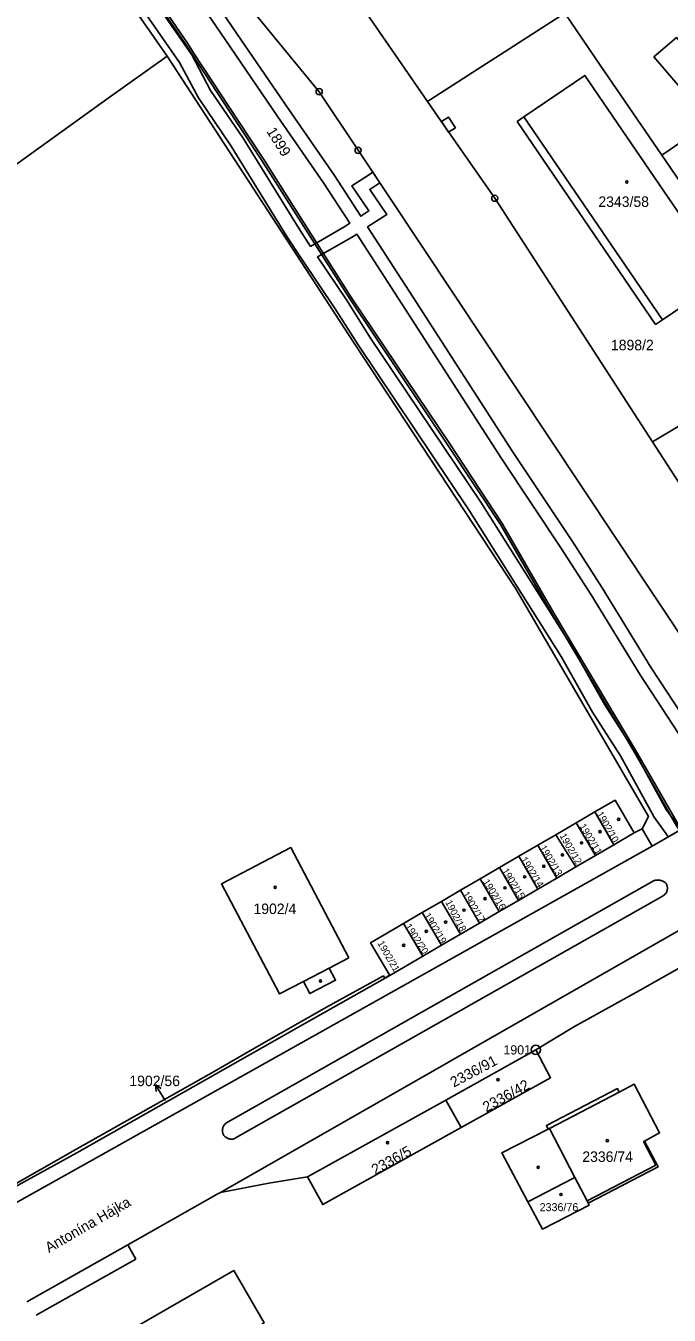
# Model space of a CAD drawing. Extents: x -821458 to -820266, y -1071458 to -1069826.
# Drawn here: x -820951.1 to -820846.6, y -1071063.4 to -1070854 of the extents above; entities that cross this region are included whole.
import ezdxf

# ---------------------------------------------------------------- set-up
doc = ezdxf.new("R2010")
doc.units = 0
for name, color, linetype in [('Vrstva 1', 7, 'Continuous'), ('Vrstva 13', 7, 'Continuous'), ('Vrstva 2', 7, 'Continuous'), ('Vrstva 4', 7, 'Continuous'), ('Vrstva 5', 7, 'Continuous'), ('Vrstva 7', 7, 'Continuous'), ('Vrstva 8', 7, 'Continuous')]:
    doc.layers.add(name, color=color, linetype=linetype)

msp = doc.modelspace()

# ---------------------------------------------------------------- linework, layer by layer
at = {"layer": 'Vrstva 1'}
for p, q in [((-820969.81, -1070799.27), (-820928.15, -1070858.94)), ((-820844.63, -1070918.75), (-820849.37, -1070921.6)), ((-820858.71, -1070981.71), (-820861.73, -1070983.47)), ((-820858.71, -1070981.71), (-820855.61, -1070987.02)), ((-820861.73, -1070983.47), (-820865.06, -1070985.41)), ((-820861.73, -1070983.47), (-820858.63, -1070988.79)), ((-820852.33, -1070985.11), (-820855.61, -1070987.02)), ((-820851.05, -1070984.42), (-820852.33, -1070985.11)), ((-820867.99, -1070987.12), (-820871.06, -1070988.91)), ((-820865.06, -1070985.41), (-820867.99, -1070987.12)), ((-820867.99, -1070987.12), (-820864.9, -1070992.44)), ((-820865.06, -1070985.41), (-820861.79, -1070990.62)), ((-820855.61, -1070987.02), (-820858.63, -1070988.79)), ((-820871.06, -1070988.91), (-820874.21, -1070990.75)), ((-820871.06, -1070988.91), (-820867.96, -1070994.22)), ((-820858.63, -1070988.79), (-820861.79, -1070990.62)), ((-820874.21, -1070990.75), (-820877.32, -1070992.56)), ((-820874.21, -1070990.75), (-820871.12, -1070996.06)), ((-820861.79, -1070990.62), (-820864.9, -1070992.44)), ((-820877.32, -1070992.56), (-820880.52, -1070994.43)), ((-820877.32, -1070992.56), (-820874.23, -1070997.88)), ((-820864.9, -1070992.44), (-820867.96, -1070994.22)), ((-820880.52, -1070994.43), (-820883.63, -1070996.24)), ((-820880.52, -1070994.43), (-820877.42, -1070999.74)), ((-820867.96, -1070994.22), (-820871.12, -1070996.06)), ((-820883.63, -1070996.24), (-820886.74, -1070998.05)), ((-820883.63, -1070996.24), (-820880.53, -1071001.55)), ((-820871.12, -1070996.06), (-820874.23, -1070997.88)), ((-820886.74, -1070998.05), (-820889.76, -1070999.81)), ((-820889.76, -1070999.81), (-820886.67, -1071005.13)), ((-820886.74, -1070998.05), (-820883.64, -1071003.36)), ((-820877.42, -1070999.74), (-820880.53, -1071001.55)), ((-820874.23, -1070997.88), (-820877.42, -1070999.74)), ((-820919.49, -1071043.49), (-820844.72, -1071000.76)), ((-820880.53, -1071001.55), (-820883.64, -1071003.36)), ((-820883.64, -1071003.36), (-820886.67, -1071005.13)), ((-820886.67, -1071005.13), (-820892.02, -1071008.25)), ((-820868.3, -1071020.34), (-820882.91, -1071028.49)), ((-820882.91, -1071028.49), (-820905.37, -1071040.98)), ((-820880.44, -1071032.95), (-820882.91, -1071028.49))]:
    msp.add_line(p, q, dxfattribs=at)
for points in [[(-821122.14, -1070589.18), (-821105.63, -1070607.47), (-821052.06, -1070666.88), (-820984.98, -1070741.28), (-820930.99, -1070801.01), (-820892.18, -1070857.22), (-820885.9, -1070866.32)], [(-820830.48, -1070974.59), (-820860.94, -1070928.75), (-820897.16, -1070874.24), (-820903.48, -1070864.73), (-820933.76, -1070827.81), (-820944.98, -1070811.53), (-820977.14, -1070776.05), (-821034.82, -1070708.07), (-821038.73, -1070703.46), (-821059.1, -1070680.77), (-821064.12, -1070689.43)], [(-820847.86, -1070875.03), (-820857.84, -1070860.4), (-820863.58, -1070851.99), (-820885.4, -1070866), (-820885.9, -1070866.32)], [(-820840.58, -1070861.56), (-820844.26, -1070864.73), (-820849.11, -1070859.07), (-820845.46, -1070855.9), (-820840.58, -1070861.56)], [(-820965.26, -1070885.48), (-820958.9, -1070880.99), (-820937.72, -1070865.8), (-820928.15, -1070858.94)], [(-820928.15, -1070858.94), (-820897.82, -1070905.55), (-820871.53, -1070945.46), (-820850.02, -1070982.46), (-820851.05, -1070984.42)], [(-820847.86, -1070875.03), (-820825.47, -1070859.75), (-820778.18, -1070926.51), (-820764.69, -1070946.15)], [(-820870.26, -1070868.82), (-820860.32, -1070862.08), (-820837.84, -1070895.04), (-820847.75, -1070901.8), (-820870.26, -1070868.82)], [(-820885.9, -1070866.32), (-820883.74, -1070869.45), (-820874.96, -1070882.02), (-820849.37, -1070921.6)], [(-820827.97, -1070904.19), (-820835.36, -1070893.35), (-820847.86, -1070875.03)], [(-820849.37, -1070921.6), (-820793.59, -1071007.77), (-820788.14, -1071016.23)], [(-820851.05, -1070984.42), (-820849.41, -1070987.24), (-820833.22, -1070977.95), (-820830.48, -1070974.59)], [(-820852.33, -1070985.11), (-820855.42, -1070979.8), (-820858.71, -1070981.71)], [(-820898.64, -1071005.39), (-820908.06, -1070987.5), (-820919.32, -1070993.38), (-820909.92, -1071011.26), (-820906, -1071009.22), (-820904.97, -1071011.2), (-820900.82, -1071009.04), (-820901.85, -1071007.06), (-820898.64, -1071005.39)], [(-820889.76, -1070999.81), (-820895.12, -1071002.94), (-820892.02, -1071008.25)], [(-820843.13, -1071005.97), (-820851.45, -1071010.71), (-820862.03, -1071016.55), (-820868.3, -1071020.34)], [(-820961.24, -1071046.82), (-820955.47, -1071043.6), (-820942.37, -1071036.15), (-820920.54, -1071023.86), (-820913.61, -1071019.85), (-820902.28, -1071013.43), (-820893.05, -1071008.32), (-820892.83, -1071008.68), (-820892.18, -1071008.26), (-820892.02, -1071008.25)], [(-820892.02, -1071008.25), (-820907.03, -1071016.77), (-820942.81, -1071037.06), (-820961.07, -1071047.07)], [(-820868.3, -1071020.34), (-820865.9, -1071024.88), (-820880.44, -1071032.95)], [(-820869.59, -1071045.02), (-820873.8, -1071037.05), (-820866.29, -1071033.22), (-820866.59, -1071032.64), (-820855.06, -1071026.62), (-820854.76, -1071027.19), (-820852.31, -1071025.92), (-820848.19, -1071033.83), (-820850.63, -1071035.15), (-820848.44, -1071039.35), (-820859.78, -1071045.23)], [(-820880.44, -1071032.95), (-820902.91, -1071045.46), (-820905.37, -1071040.98)], [(-820905.37, -1071040.98), (-820911.64, -1071041.98), (-820919.49, -1071043.49)], [(-820869.59, -1071045.02), (-820862.16, -1071041.17), (-820861.94, -1071041.06), (-820859.98, -1071044.84), (-820859.78, -1071045.23)], [(-820950.97, -1071061.24), (-820934.57, -1071052), (-820920.03, -1071043.8), (-820919.49, -1071043.49)], [(-820859.78, -1071045.23), (-820859.61, -1071045.55), (-820867.22, -1071049.45), (-820869.59, -1071045.02)], [(-820943.73, -1071071.4), (-820917.31, -1071056.2), (-820912.42, -1071064.7), (-820912.82, -1071064.94), (-820911.69, -1071066.91)]]:
    msp.add_lwpolyline(points, dxfattribs=at)
at = {"layer": 'Vrstva 13'}
for points in [[(-820904.89, -1070889.85), (-820906.75, -1070887.02), (-820915.84, -1070872.29), (-820921.1, -1070864.54), (-820924.16, -1070858.76), (-820935.49, -1070842.47), (-820940.7, -1070835.15), (-820950.45, -1070822.13), (-820960.57, -1070807.59), (-820967.99, -1070796.51), (-820968.45, -1070795.86), (-820964.16, -1070792.35), (-820957.12, -1070802.08), (-820946.13, -1070816.91), (-820939.51, -1070826.31), (-820927.43, -1070843.51), (-820917.95, -1070857.45), (-820910.17, -1070868.83), (-820902.77, -1070879.51), (-820898.51, -1070886.1), (-820899.32, -1070886.63)], [(-820883.64, -1070869.59), (-820882.46, -1070871.28), (-820881.36, -1070870.58), (-820882.48, -1070868.84)]]:
    msp.add_lwpolyline(points, close=True, dxfattribs=at)
for points in [[(-820952.33, -1070823.49), (-820942.57, -1070836.51), (-820937.39, -1070843.81), (-820926.14, -1070859.96), (-820923.08, -1070865.74), (-820917.78, -1070873.55), (-820908.71, -1070888.26), (-820906.28, -1070891.93), (-820900.9, -1070899.97), (-820897.17, -1070905.83), (-820879.17, -1070932.66), (-820864.17, -1070956.47), (-820859.08, -1070965.49), (-820854.56, -1070972.59), (-820849.07, -1070982.53), (-820847.11, -1070985.26), (-820846.8, -1070985.75)], [(-820938.14, -1070838.08), (-820925.14, -1070857.05), (-820924.16, -1070858.58), (-820916.97, -1070869.55), (-820912.9, -1070875.75), (-820898.52, -1070898.39), (-820882.58, -1070922.11), (-820874.06, -1070935.01), (-820865.34, -1070950.13), (-820852.23, -1070972.12), (-820845.45, -1070983.96), (-820844.95, -1070984.68), (-820844.65, -1070984.51), (-820845.15, -1070983.78), (-820851.93, -1070971.94), (-820865.04, -1070949.95), (-820873.76, -1070934.83), (-820882.28, -1070921.91), (-820898.22, -1070898.19), (-820912.6, -1070875.55), (-820916.67, -1070869.36), (-820923.86, -1070858.39), (-820924.84, -1070856.86), (-820937.9, -1070837.8)], [(-820839.74, -1070973.3), (-820849.58, -1070958.3), (-820857.55, -1070945.31), (-820862.35, -1070937.79), (-820872.11, -1070923.15), (-820888.28, -1070898.06), (-820895.62, -1070886.69), (-820892.5, -1070884.66), (-820895.27, -1070880.6), (-820894.13, -1070879.86), (-820893.65, -1070879.52), (-820894.79, -1070877.8), (-820895.29, -1070878.16), (-820898.17, -1070880), (-820895.4, -1070884.08), (-820896.74, -1070884.95), (-820901.01, -1070878.33), (-820908.43, -1070867.63), (-820916.21, -1070856.27), (-820925.69, -1070842.31)], [(-820845.19, -1070983.96), (-820847.11, -1070981.29), (-820852.56, -1070971.41), (-820857.1, -1070964.29), (-820862.19, -1070955.29), (-820877.23, -1070931.4), (-820895.23, -1070904.57), (-820898.96, -1070898.71), (-820903.74, -1070891.57), (-820898.24, -1070888.39), (-820897.39, -1070887.84), (-820890.06, -1070899.2), (-820873.87, -1070924.31), (-820864.11, -1070938.95), (-820859.33, -1070946.43), (-820851.36, -1070959.44), (-820841.54, -1070974.42)], [(-820846.8, -1070985.75), (-820844.8, -1070984.59)]]:
    msp.add_lwpolyline(points, dxfattribs=at)
at = {"layer": 'Vrstva 4'}
for p, q in [((-820870.26, -1070868.82), (-820871.35, -1070869.56)), ((-820871.35, -1070869.56), (-820848.84, -1070902.54)), ((-820848.84, -1070902.54), (-820847.75, -1070901.8)), ((-820849.41, -1070987.24), (-820941.72, -1071039.04)), ((-820918.61, -1071032.23), (-820849.07, -1070992.85)), ((-820847.6, -1070995.3), (-820917.31, -1071034.81)), ((-820901.85, -1071007.06), (-820906, -1071009.22)), ((-820866.06, -1071033.1), (-820854.76, -1071027.19)), ((-820866.29, -1071033.22), (-820866.06, -1071033.1)), ((-820866.06, -1071033.1), (-820861.94, -1071041.06)), ((-820850.81, -1071035.25), (-820850.63, -1071035.15)), ((-820848.82, -1071039.05), (-820850.81, -1071035.25)), ((-820941.72, -1071039.04), (-820959.66, -1071049.05)), ((-820859.98, -1071044.84), (-820848.82, -1071039.05)), ((-820934.57, -1071052), (-820933.26, -1071054.33)), ((-820933.26, -1071054.33), (-820949.41, -1071063.43))]:
    msp.add_line(p, q, dxfattribs=at)
for points in [[(-820849.07, -1070992.85), (-820848.96, -1070992.82), (-820848.84, -1070992.79), (-820848.73, -1070992.77), (-820848.61, -1070992.76), (-820848.49, -1070992.75), (-820848.38, -1070992.76), (-820848.26, -1070992.77), (-820848.14, -1070992.78), (-820848.03, -1070992.81), (-820847.92, -1070992.84), (-820847.81, -1070992.88), (-820847.7, -1070992.93), (-820847.59, -1070992.98), (-820847.49, -1070993.04), (-820847.39, -1070993.11), (-820847.3, -1070993.18), (-820847.21, -1070993.26), (-820847.13, -1070993.34)], [(-820847.13, -1070993.34), (-820847.08, -1070993.43), (-820847.04, -1070993.53), (-820847, -1070993.63), (-820846.97, -1070993.73), (-820846.95, -1070993.84), (-820846.93, -1070993.94), (-820846.93, -1070994.05), (-820846.93, -1070994.15), (-820846.94, -1070994.26), (-820846.96, -1070994.36), (-820846.98, -1070994.47), (-820847.01, -1070994.57), (-820847.05, -1070994.67), (-820847.1, -1070994.76), (-820847.15, -1070994.85), (-820847.21, -1070994.94), (-820847.28, -1070995.02), (-820847.35, -1070995.1), (-820847.43, -1070995.17), (-820847.51, -1070995.24), (-820847.6, -1070995.3)], [(-820919.07, -1071034.05), (-820919.11, -1071033.95), (-820919.14, -1071033.84), (-820919.16, -1071033.73), (-820919.18, -1071033.62), (-820919.18, -1071033.51), (-820919.18, -1071033.4), (-820919.17, -1071033.28), (-820919.16, -1071033.18), (-820919.13, -1071033.07), (-820919.1, -1071032.96), (-820919.06, -1071032.85), (-820919.02, -1071032.75), (-820918.97, -1071032.65), (-820918.91, -1071032.56), (-820918.84, -1071032.47), (-820918.77, -1071032.39), (-820918.69, -1071032.3), (-820918.61, -1071032.23)], [(-820917.31, -1071034.81), (-820917.42, -1071034.83), (-820917.52, -1071034.84), (-820917.63, -1071034.85), (-820917.74, -1071034.85), (-820917.85, -1071034.84), (-820917.95, -1071034.83), (-820918.06, -1071034.8), (-820918.16, -1071034.77), (-820918.27, -1071034.74), (-820918.36, -1071034.7), (-820918.46, -1071034.65), (-820918.55, -1071034.59), (-820918.64, -1071034.53), (-820918.72, -1071034.46), (-820918.81, -1071034.39), (-820918.88, -1071034.31), (-820918.95, -1071034.23), (-820919.01, -1071034.14), (-820919.07, -1071034.05)]]:
    msp.add_lwpolyline(points, dxfattribs=at)
at = {"layer": 'Vrstva 5'}
for centre in [(-820853.52, -1070879.4), (-820854.85, -1070982.91), (-820857.88, -1070984.9), (-820860.87, -1070986.71), (-820863.98, -1070988.68), (-820867.01, -1070990.52), (-820870.12, -1070992.25), (-820910.62, -1070993.94), (-820876.56, -1070995.78), (-820873.3, -1070994.02), (-820879.96, -1070997.65), (-820882.94, -1070999.59), (-820886.09, -1071001.08), (-820889.75, -1071003.37), (-820903.26, -1071009.15), (-820874.43, -1071025.19), (-820892.37, -1071035.42), (-820856.69, -1071035.08), (-820867.92, -1071039.41), (-820864.22, -1071043.84)]:
    msp.add_circle(centre, 0.175, dxfattribs=at)
at = {"layer": 'Vrstva 7'}
for p, q in [((-820928.48, -1071028.56), (-820930.07, -1071026.02)), ((-820930.07, -1071026.02), (-820929.11, -1071026.6)), ((-820930.07, -1071026.02), (-820929.96, -1071027.13))]:
    msp.add_line(p, q, dxfattribs=at)
at = {"layer": 'Vrstva 8'}
for centre, radius in [((-820903.48, -1070864.73), 0.5), ((-820903.48, -1070864.73), 0.0303), ((-820897.16, -1070874.24), 0.5), ((-820897.16, -1070874.24), 0.0303), ((-820874.96, -1070882.02), 0.5), ((-820874.96, -1070882.02), 0.0303), ((-820868.3, -1071020.34), 0.75), ((-820868.3, -1071020.34), 0.03)]:
    msp.add_circle(centre, radius, dxfattribs=at)

# ---------------------------------------------------------------- texts
at = {"layer": 'Vrstva 2'}
for s, height, rotation, p in [('1899', 1.7, 302, (-820912.1, -1070871.15)), ('1902/10', 1.139, 300, (-820858.47, -1070982.02)), ('1902/12', 1.139, 300, (-820864.48, -1070985.57)), ('1902/11', 1.139, 301, (-820861.27, -1070984.03)), ('1902/13', 1.139, 301, (-820867.72, -1070987.51)), ('1902/14', 1.139, 302, (-820870.82, -1070989.42)), ('1902/15', 1.139, 302, (-820873.85, -1070991.28)), ('1902/16', 1.139, 302, (-820876.95, -1070993.05)), ('1902/17', 1.139, 301, (-820880.26, -1070995.04)), ('1902/18', 1.139, 297, (-820883.04, -1070996.36)), ('1902/20', 1.139, 303, (-820889.59, -1071000.3)), ('1902/19', 1.139, 301, (-820886.51, -1070998.51)), ('1902/21', 1.139, 300, (-820894.06, -1071003.02)), ('2336/91', 1.7, 28, (-820881.63, -1071026.49)), ('2336/42', 1.7, 29, (-820876.33, -1071030.53)), ('2336/5', 1.7, 29, (-820894.39, -1071040.69))]:
    msp.add_text(s, height=height, rotation=rotation, dxfattribs=at).set_placement(p)
for s, height, p in [('2343/58', 1.7, (-820858.14, -1070883.44)), ('1898/2', 1.7, (-820856.1, -1070906.72)), ('1902/4', 1.7, (-820914.15, -1070998.28)), ('1902/56', 1.7, (-820934.3, -1071026.23)), ('2336/74', 1.7, (-820860.75, -1071038.54)), ('2336/76', 1.3, (-820867.68, -1071046.54))]:
    msp.add_text(s, height=height, dxfattribs=at).set_placement(p)
at = {"layer": 'Vrstva 7'}
msp.add_text('Antonína Hájka', height=1.7, rotation=30, dxfattribs=at).set_placement((-820947.36, -1071053.34))
at = {"layer": 'Vrstva 8'}
msp.add_text('1901', height=1.5, dxfattribs=at).set_placement((-820873.55, -1071021.09))

doc.saveas('drawing.dxf')
